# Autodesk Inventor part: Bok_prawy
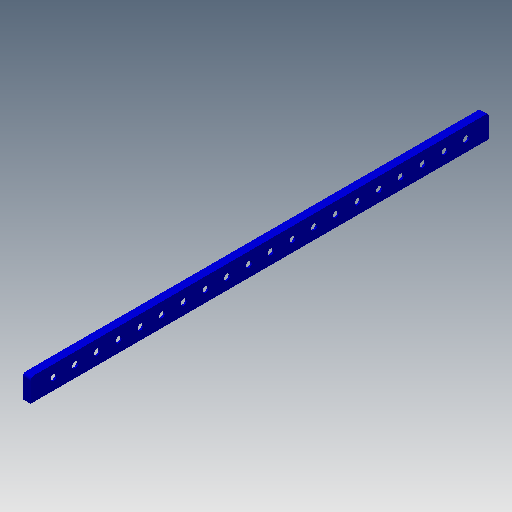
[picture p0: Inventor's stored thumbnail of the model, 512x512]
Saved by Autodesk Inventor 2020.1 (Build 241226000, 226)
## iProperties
Created: 2005-09
Part Number: Bok_prawy
Document SubType Name: Modeling
Description: Bok przenośnika - prawy
Density: 1 g/cm^3
Material: Ogólny
Appearance: Niebieski
Mass: 6745.11 g
Surface Area: 14374 cm^2
Volume: 6745.11 cm^3
Designer: F.Stasiak
Manager: www.cadconsulting.pl
Company: Fabian Stasiak CAD Consulting
Author: F.Stasiak
Subject: Zbiór ćwiczeń. Autodesk Inventor 2020. Kurs podstawowy
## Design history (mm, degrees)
sketch "Szkic1"
  geometry: L1 (0, 0)-(-50, 0); L2 (-50, 0)-(-50, 150); L3 (-50, 150)-(0, 150); L4 (0, 150)-(0, 0)
  constraints: 8 end point, 2 parallel, 1 horizontal, 1 perpendicular
  dimensions: "d0" = 150 distance of L1.end L2.end; "d1" = 50 distance of L1.start L1.end
extrude "Wyciągnięcie proste1" new body sketch "Szkic1" distance "d3" = 3000 (= DŁUGOŚĆ); taper "d4" = 0 deg
fillet "Zaokrąglenie1" dims "d16" = 20
fillet "Zaokrąglenie2" dims "d17" = 20
feature "Skorupa1" dims "d18" = 10
sketch "Szkic2"
  geometry: L1 (0, 0)-(0, 150) reference; L2 (3000, 0)-(3000, 150) reference; L3 (0, 75)-(3000, 75); 1 further point
  constraints: 2 end point, 2 midpoint, 1 point on line
  dimensions: "d5" = 150 distance from line of point (150, 75) L1
hole "Otwór1" sketch "Szkic2" at (150, 75) diameter "d6" = 40; stored, may be unused: countersink angle "d10" = 90 deg, drill point angle "d12" = 118 deg; dims "d7" = 6, "d8" = 4, "d9" = 2, "d11" = 8
node "Otwory3"
node "Otwory4"
node "Bryła1"
node "Korpusy bryłowe"
node "Korpusy powierzchniowe"
pattern_linear "Szyk prostokątny1" dims "d15" = 2700 (computed from DŁUGOŚĆ)
sketch "Szkic5"
  geometry: 1 further point
hole "Hole4" sketch "Szkic5" diameter "d33" = 6.647; stored, may be unused: countersink angle "d37" = 90 deg, drill point angle "d39" = 120 deg; dims "d34" = 18.9, "d35" = 4, "d36" = 2, "d38" = 22.9
sketch "Szkic6"
  geometry: 1 further point
hole "Hole5" sketch "Szkic6" diameter "d40" = 6.647; stored, may be unused: countersink angle "d44" = 90 deg, drill point angle "d46" = 120 deg; dims "d41" = 18.9, "d42" = 4, "d43" = 2, "d45" = 22.9
other parameters: "DŁUGOŚĆ" = 3000 [user parameter; used in 3 equation terms]
